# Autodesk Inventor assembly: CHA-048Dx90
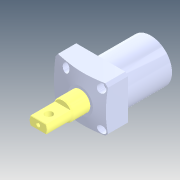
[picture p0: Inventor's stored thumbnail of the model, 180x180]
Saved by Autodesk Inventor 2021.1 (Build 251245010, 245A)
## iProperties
Created: 2018-07
Part Number: CHA-048Dx90
Description: STEP AP214
Document SubType Name: Assembly
Designer: user
Title: CHA-048Dx90(Ë«±Û£©.STEP
Revision Number: ÈÎºÎ
Sending System: SolidWorks 2016
Preprocessor: SwSTEP 2.0
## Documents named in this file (3)
- D:\Vault_2016\Projekty\Clamptek\Hydraulic\CHA\CHA\CHA-048\Inventor\CHA-048Dx90\CHA-048Dx90.iam
- D:\Vault_2016\Projekty\Clamptek\Hydraulic\CHA\CHA\CHA-048\Inventor\CHA-048Dx90\CHA-048±¾Ìå.ipt
- D:\Vault_2016\Projekty\Clamptek\Hydraulic\CHA\CHA\CHA-048\Inventor\CHA-048Dx90\CHA-048D(Ë«±Û£©»îÈû¸Ë.ipt
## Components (2 placed, 2 different names)
1. CHA-048±¾Ìå_1
2. CHA-048D(Ë«±Û£©»îÈû¸Ë_2
